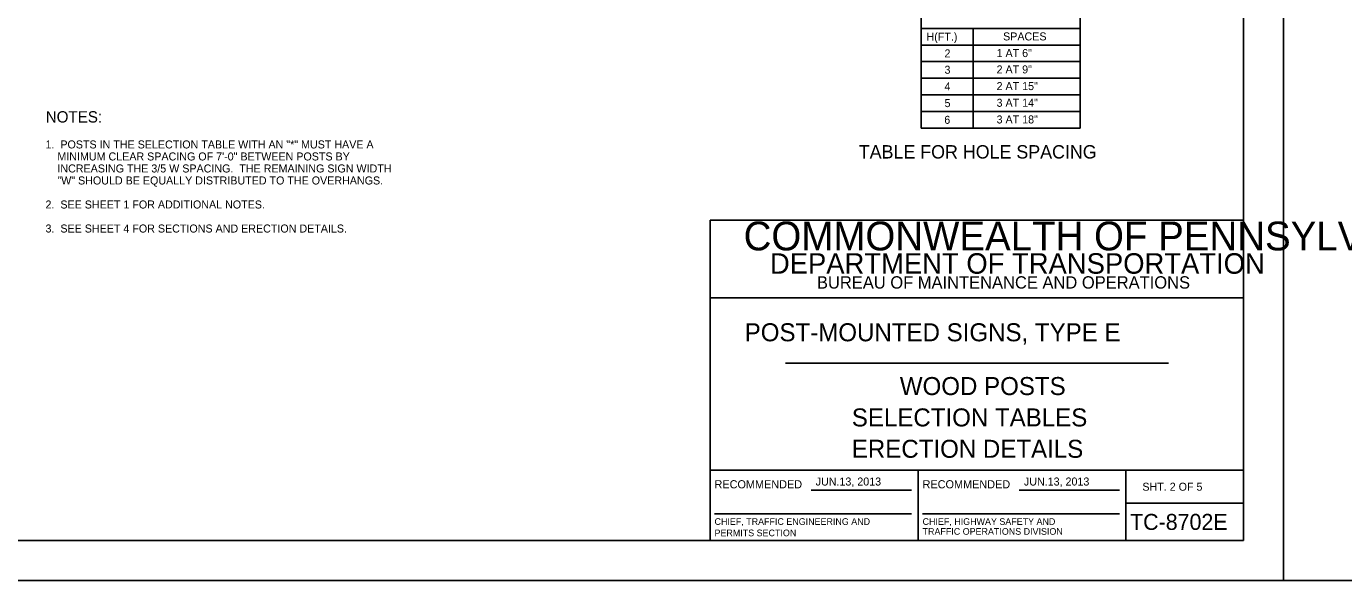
# Model space of a CAD drawing. Extents: x -2340 to 628, y -879 to 309.
# Drawn here: x -747.7 to -253.8, y -284.6 to -76.9 of the extents above; entities that cross this region are included whole.
import ezdxf

# ---------------------------------------------------------------- set-up
doc = ezdxf.new("R2010")
doc.units = 0
for name, color, linetype in [('Level 1', 7, 'Continuous'), ('Level 2', 7, 'Continuous'), ('Level 3', 7, 'Continuous'), ('Level 4', 7, 'Continuous'), ('PLT-BNDY', 7, 'Continuous')]:
    doc.layers.add(name, color=color, linetype=linetype)

msp = doc.modelspace()

# ---------------------------------------------------------------- linework, layer by layer
at = {"layer": 'Level 1'}
for p, q in [((-291.39, -269.56), (-291.39, 294.44)), ((-491.39, -269.56), (-491.39, -149.56)), ((-491.39, -149.56), (-291.39, -149.56)), ((-291.39, -178.56), (-491.39, -178.56)), ((-463.14, -203.06), (-319.51, -203.06)), ((-491.39, -243.19), (-291.39, -243.19)), ((-413.39, -243.19), (-413.39, -269.56)), ((-335.51, -269.56), (-335.51, -243.19)), ((-453.45, -250.62), (-415.83, -250.62)), ((-375.45, -250.62), (-337.83, -250.62)), ((-335.51, -255.56), (-291.39, -255.56)), ((-489.7, -259.51), (-415.83, -259.51)), ((-411.7, -259.51), (-337.83, -259.51)), ((-291.39, -269.56), (-1077.39, -269.56)), ((-1077.39, -269.56), (-491.39, -269.56))]:
    msp.add_line(p, q, dxfattribs=at)
at = {"layer": 'Level 2'}
for p, q in [((-412.17, -115.03), (-412.17, -65.16)), ((-352.67, -115.03), (-352.67, -65.16)), ((-352.67, -77.66), (-412.17, -77.66)), ((-392.79, -115.03), (-392.79, -77.66)), ((-352.67, -83.91), (-412.17, -83.91)), ((-352.67, -90.03), (-412.17, -90.03)), ((-352.67, -96.28), (-412.17, -96.28)), ((-352.67, -102.53), (-412.17, -102.53)), ((-352.67, -108.78), (-412.17, -108.78)), ((-352.67, -115.03), (-412.17, -115.03))]:
    msp.add_line(p, q, dxfattribs=at)
at = {"layer": 'PLT-BNDY'}
for points in [[(-1117.39, 309.44), (-276.39, 309.44), (-276.39, -284.56), (-1117.39, -284.56)], [(-276.39, 309.44), (564.61, 309.44), (564.61, -284.56), (-276.39, -284.56)]]:
    msp.add_lwpolyline(points, close=True, dxfattribs=at)

# ---------------------------------------------------------------- texts
at = {"layer": 'Level 1'}
for s, height, p in [('COMMONWEALTH OF PENNSYLVANIA', 10.7827, (-478.79, -160.83)), ('DEPARTMENT OF TRANSPORTATION', 7.6838, (-468.93, -169.58)), ('BUREAU OF MAINTENANCE AND OPERATIONS', 4.6252, (-451.29, -175.15)), ('POST-MOUNTED SIGNS, TYPE E', 6.7492, (-478.39, -194.89)), ('WOOD POSTS', 6.75, (-420.23, -215.04)), ('SELECTION TABLES', 6.75, (-438.23, -226.79)), ('ERECTION DETAILS', 6.75, (-438.23, -238.54)), ('RECOMMENDED', 3.048, (-489.7, -249.99)), ('RECOMMENDED', 3.048, (-411.7, -249.99)), ('SHT. 2 OF 5', 3, (-329.3, -250.88)), ('CHIEF, TRAFFIC ENGINEERING AND', 2.5, (-489.7, -263.68)), ('CHIEF, HIGHWAY SAFETY AND', 2.5, (-411.7, -263.68)), ('TC-8702E', 6, (-333.91, -265.56)), ('PERMITS SECTION', 2.5, (-489.7, -267.93)), ('TRAFFIC OPERATIONS DIVISION', 2.5, (-411.7, -267.38))]:
    msp.add_text(s, height=height, dxfattribs=at).set_placement(p)
at = {"layer": 'Level 2'}
for p in [(-451.78, -248.93), (-373.71, -248.93)]:
    msp.add_text('JUN.13, 2013', height=3, dxfattribs=at).set_placement(p)
at = {"layer": 'Level 3'}
for s, height, p in [('H(FT.)', 3, (-410.23, -82.28)), ('SPACES', 3, (-381.51, -82.17)), ('2', 3, (-403.48, -88.53)), ('1 AT 6"', 3, (-383.96, -88.41)), ('3', 3, (-403.48, -94.66)), ('2 AT 9"', 3, (-383.96, -94.53)), ('4', 3, (-403.48, -100.91)), ('2 AT 15"', 3, (-383.96, -100.78)), ('NOTES:', 4.25, (-740.43, -112.93)), ('5', 3, (-403.48, -107.16)), ('3 AT 14"', 3, (-383.96, -107.03)), ('6', 3, (-403.56, -113.41)), ('3 AT 18"', 3, (-383.96, -113.28)), ('TABLE FOR HOLE SPACING', 5, (-435.61, -126.41))]:
    msp.add_text(s, height=height, dxfattribs=at).set_placement(p)
at = {"layer": 'Level 4'}
for s, p in [('1.  POSTS IN THE SELECTION TABLE WITH AN "*" MUST HAVE A', (-740.51, -122.64)), ('    MINIMUM CLEAR SPACING OF 7\'-0" BETWEEN POSTS BY', (-740.51, -127.14)), ('    "W" SHOULD BE EQUALLY DISTRIBUTED TO THE OVERHANGS.', (-740.51, -136.14)), ('    INCREASING THE 3/5 W SPACING.  THE REMAINING SIGN WIDTH', (-740.51, -131.64)), ('2.  SEE SHEET 1 FOR ADDITIONAL NOTES.', (-740.51, -145.14)), ('3.  SEE SHEET 4 FOR SECTIONS AND ERECTION DETAILS.', (-740.51, -154.14))]:
    msp.add_text(s, height=3, dxfattribs=at).set_placement(p)

doc.saveas('drawing.dxf')
